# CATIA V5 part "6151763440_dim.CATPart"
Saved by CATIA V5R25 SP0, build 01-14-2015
Part number: 6151763440_dim
Source: made
Property "PROI_CREATED_ON": "12/17/2008 9:21:37 AM"
Property "BLANK_DRAWING": "--"
Property "DRAWN_BY": "ALG"
Property "FINISH": "--"
Property "HEAT_TREATMENT": "ASSIGN"
Property "MATERIAL": "ASSIGN"
Property "PROJECT": "--"
Property "PROTOTYPE_NO": "--"
Property "RELATED_DRAWING": "--"
Property "COMPLETE_MATERIAL": "ASSIGN-ASSIGN"
Property "DESCRIPTION": "XPBM-6000-P"
Property "DRAWING_EXIST": "--"
Property "MANUFACTURER": "--"
Property "MANUFACTURER_2": "--"
Property "MANUFACTURER_REF": "--"
Property "TYPE_PART": "A"
Property "TODAY_DATE": "2023/06/07"
Property "PDMREV": "01.2"
Property "PDMRL": "Production"
Property "PROI_REVISION": "01"
Property "PROI_VERSION": "2"
Property "PROI_RELEASE": "Production"
Property "PTC_MODIFIED": false
Property "MFG_WP_MATERIAL": "ASSIGN"
Property "COMPANY_CODE": "---"
Property "DESCRIPTION_JP": "--"
Property "PQP_DOCUMENT": "--"
Property "SUPPLIER": "--"
Property "REFERENCE": "6151763440"
Property "PTC_WM_REVISION": "01"
Property "PTC_WM_ITERATION": "2"
Property "PTC_WM_VERSION": "01.2"
Property "PTC_WM_LIFECYCLE_STATE": "Production"
Property "PTC_WM_LIFECYCLE": "Design_Process"
Property "PTC_WM_LOCATION": "/Products/DRILLS TOOLS ASC/A1780 - XPB/9-01-Dimensional Drawings and 3D"
Property "PTC_WM_CREATED_BY": "Alain Le Goc (grealg) (grealg: CPD)"
Property "PTC_WM_CREATED_ON": "07-Jun-23 04:03:55 PM"
Property "PTC_WM_MODIFIED_BY": "Alain Le Goc (grealg) (grealg: CPD)"
Property "PTC_WM_MODIFIED_ON": "08-Jun-23 03:52:16 PM"
Property "PTC_WM_TEAM": "Default"
Property "PTC_ORGANIZATION_ID": "CPD"
Property "EXPORT_CONTROL": "NULL"
Property "PTC_WM_NAME": "6151763440_dim.prt"
Property "PTC_WM_NUMBER": "6151763440_DIM.PRT"
Property "PTC_COMMON_NAME": "6151763440_dim.prt"
Property "PTC_MASTER_MATERIAL": "ASSIGN"
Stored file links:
  d:\ptc\Echange\temp\6151763440_dim.CATPart

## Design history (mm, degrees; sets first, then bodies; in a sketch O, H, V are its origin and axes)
AxisSystem1 "CS0": origin (0, 0, 0), X (1, 0, 0), Y (0, 1, 0), Z (0, 0, 1)
Set1
  DatumSurface1 "Sheet.1"
  DatumSurface2 "Sheet.2"
  DatumSurface3 "Sheet.3"
  DatumSurface4 "Sheet.4"
  DatumSurface5 "Sheet.5"
  DatumSurface6 "Sheet.6"
  DatumSurface7 "Sheet.7"
  DatumSurface8 "Sheet.8"
  DatumSurface9 "Sheet.9"
  DatumSurface10 "Sheet.10"
  DatumSurface11 "Sheet.11"
  DatumSurface12 "Sheet.12"
  DatumSurface13 "Sheet.13"
  DatumSurface14 "Sheet.14"
  DatumSurface15 "Sheet.15"
  DatumSurface16 "Sheet.16"
  DatumSurface17 "Sheet.17"
  DatumSurface18 "Sheet.18"
  DatumSurface19 "Sheet.19"
  DatumSurface20 "Sheet.20"
  DatumSurface21 "Sheet.21"
  DatumSurface22 "Sheet.22"
  DatumSurface23 "Sheet.23"
  DatumSurface24 "Sheet.24"
  DatumSurface25 "Sheet.25"
  DatumSurface26 "Sheet.26"
  DatumSurface27 "Sheet.27"
  DatumSurface28 "Sheet.28"
  DatumSurface29 "Sheet.29"
  DatumSurface30 "Sheet.30"
  DatumSurface31 "Sheet.31"
  DatumSurface32 "Sheet.32"
  DatumSurface33 "Sheet.33"
  DatumSurface34 "Sheet.34"
  DatumSurface35 "Sheet.35"
  DatumSurface36 "Sheet.36"
  DatumSurface37 "Sheet.37"
  DatumSurface38 "Sheet.38"
  DatumSurface39 "Sheet.39"
  DatumSurface40 "Sheet.40"
  DatumSurface41 "Sheet.41"
  DatumSurface42 "Sheet.42"
  Plane1 "RIGHT": stored without definition
  Plane2 "TOP": stored without definition
  Plane3 "FRONT": stored without definition
Body1 "PartBody" (main body)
